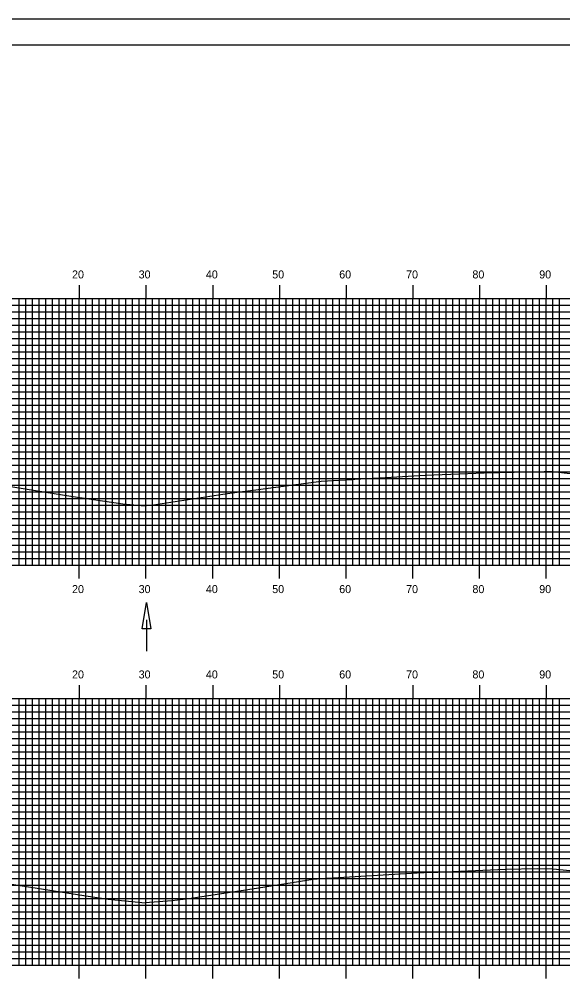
# Model space of a CAD drawing. Extents: x 851926 to 852269, y 366605 to 366825.
# Drawn here: x 852103 to 852184.5, y 366680.6 to 366824.9 of the extents above; entities that cross this region are included whole.
import ezdxf

# ---------------------------------------------------------------- set-up
doc = ezdxf.new("R2010")
doc.units = 0
for name, color, linetype in [('BORDER', 7, 'Continuous'), ('D_Drainage_Ditch_Line', 7, 'Continuous'), ('H_V ANNOTATION', 7, 'Continuous'), ('M_Roadway_Centerline', 7, 'Continuous'), ('MAJOR', 7, 'Continuous'), ('MINOR', 7, 'Continuous'), ('PLOT BOUNDARY', 7, 'Continuous'), ('S_Roadway_Centerline', 7, 'Continuous')]:
    doc.layers.add(name, color=color, linetype=linetype)

msp = doc.modelspace()

# ---------------------------------------------------------------- linework, layer by layer
at = {"layer": 'BORDER'}
msp.add_lwpolyline([(851942.36, 366611.06), (852262.36, 366611.06), (852262.36, 366821.06), (851942.36, 366821.06)], close=True, dxfattribs=at)
at = {"layer": 'D_Drainage_Ditch_Line'}
msp.add_line((852122.03, 366734.83), (852122.03, 366730.13), dxfattribs=at)
msp.add_lwpolyline([(852122.68, 366733.52), (852121.37, 366733.52), (852122.03, 366737.45)], close=True, dxfattribs=at)
at = {"layer": 'MAJOR'}
for p, q in [((852111.96, 366785.06), (852111.96, 366783.06)), ((852121.96, 366785.06), (852121.96, 366783.06)), ((852131.96, 366785.06), (852131.96, 366783.06)), ((852141.96, 366785.06), (852141.96, 366783.06)), ((852151.96, 366785.06), (852151.96, 366783.06)), ((852161.96, 366785.06), (852161.96, 366783.06)), ((852171.96, 366785.06), (852171.96, 366783.06)), ((852181.96, 366785.06), (852181.96, 366783.06)), ((851951.96, 366783.06), (852231.96, 366783.06)), ((851951.96, 366783.06), (852231.96, 366783.06)), ((852111.96, 366743.06), (852111.96, 366783.06)), ((852121.96, 366743.06), (852121.96, 366783.06)), ((852131.96, 366743.06), (852131.96, 366783.06)), ((852141.96, 366743.06), (852141.96, 366783.06)), ((852151.96, 366743.06), (852151.96, 366783.06)), ((852161.96, 366743.06), (852161.96, 366783.06)), ((852171.96, 366743.06), (852171.96, 366783.06)), ((852181.96, 366743.06), (852181.96, 366783.06)), ((851951.96, 366778.06), (852231.96, 366778.06)), ((851951.96, 366773.06), (852231.96, 366773.06)), ((851951.96, 366768.06), (852231.96, 366768.06)), ((851951.96, 366763.06), (852231.96, 366763.06)), ((851951.96, 366758.06), (852231.96, 366758.06)), ((851951.96, 366753.06), (852231.96, 366753.06)), ((851951.96, 366748.06), (852231.96, 366748.06)), ((851951.96, 366743.06), (852231.96, 366743.06)), ((851951.96, 366743.06), (852231.96, 366743.06)), ((852111.96, 366741.05), (852111.96, 366743.06)), ((852121.96, 366741.05), (852121.96, 366743.06)), ((852131.96, 366741.05), (852131.96, 366743.06)), ((852141.96, 366741.05), (852141.96, 366743.06)), ((852151.96, 366741.05), (852151.96, 366743.06)), ((852161.96, 366741.05), (852161.96, 366743.06)), ((852171.96, 366741.05), (852171.96, 366743.06)), ((852181.96, 366741.05), (852181.96, 366743.06)), ((852111.96, 366725.06), (852111.96, 366723.06)), ((852121.96, 366725.06), (852121.96, 366723.06)), ((852131.96, 366725.06), (852131.96, 366723.06)), ((852141.96, 366725.06), (852141.96, 366723.06)), ((852151.96, 366725.06), (852151.96, 366723.06)), ((852161.96, 366725.06), (852161.96, 366723.06)), ((852171.96, 366725.06), (852171.96, 366723.06)), ((852181.96, 366725.06), (852181.96, 366723.06)), ((851951.96, 366723.06), (852231.96, 366723.06)), ((851951.96, 366723.06), (852231.96, 366723.06)), ((852111.96, 366683.06), (852111.96, 366723.06)), ((852121.96, 366683.06), (852121.96, 366723.06)), ((852131.96, 366683.06), (852131.96, 366723.06)), ((852141.96, 366683.06), (852141.96, 366723.06)), ((852151.96, 366683.06), (852151.96, 366723.06)), ((852161.96, 366683.06), (852161.96, 366723.06)), ((852171.96, 366683.06), (852171.96, 366723.06)), ((852181.96, 366683.06), (852181.96, 366723.06)), ((851951.96, 366718.06), (852231.96, 366718.06)), ((851951.96, 366713.06), (852231.96, 366713.06)), ((851951.96, 366708.06), (852231.96, 366708.06)), ((851951.96, 366703.06), (852231.96, 366703.06)), ((851951.96, 366698.06), (852231.96, 366698.06)), ((851951.96, 366693.06), (852231.96, 366693.06)), ((851951.96, 366688.06), (852231.96, 366688.06)), ((851951.96, 366683.06), (852231.96, 366683.06)), ((851951.96, 366683.06), (852231.96, 366683.06)), ((852111.96, 366681.05), (852111.96, 366683.06)), ((852121.96, 366681.05), (852121.96, 366683.06)), ((852131.96, 366681.05), (852131.96, 366683.06)), ((852141.96, 366681.05), (852141.96, 366683.06)), ((852151.96, 366681.05), (852151.96, 366683.06)), ((852161.96, 366681.05), (852161.96, 366683.06)), ((852171.96, 366681.05), (852171.96, 366683.06)), ((852181.96, 366681.05), (852181.96, 366683.06))]:
    msp.add_line(p, q, dxfattribs=at)
at = {"layer": 'MINOR'}
for p, q in [((852102.96, 366743.06), (852102.96, 366783.06)), ((852103.96, 366743.06), (852103.96, 366783.06)), ((852104.96, 366743.06), (852104.96, 366783.06)), ((852105.96, 366743.06), (852105.96, 366783.06)), ((852106.96, 366743.06), (852106.96, 366783.06)), ((852107.96, 366743.06), (852107.96, 366783.06)), ((852108.96, 366743.06), (852108.96, 366783.06)), ((852109.96, 366743.06), (852109.96, 366783.06)), ((852110.96, 366743.06), (852110.96, 366783.06)), ((852112.96, 366743.06), (852112.96, 366783.06)), ((852113.96, 366743.06), (852113.96, 366783.06)), ((852114.96, 366743.06), (852114.96, 366783.06)), ((852115.96, 366743.06), (852115.96, 366783.06)), ((852116.96, 366743.06), (852116.96, 366783.06)), ((852117.96, 366743.06), (852117.96, 366783.06)), ((852118.96, 366743.06), (852118.96, 366783.06)), ((852119.96, 366743.06), (852119.96, 366783.06)), ((852120.96, 366743.06), (852120.96, 366783.06)), ((852122.96, 366743.06), (852122.96, 366783.06)), ((852123.96, 366743.06), (852123.96, 366783.06)), ((852124.96, 366743.06), (852124.96, 366783.06)), ((852125.96, 366743.06), (852125.96, 366783.06)), ((852126.96, 366743.06), (852126.96, 366783.06)), ((852127.96, 366743.06), (852127.96, 366783.06)), ((852128.96, 366743.06), (852128.96, 366783.06)), ((852129.96, 366743.06), (852129.96, 366783.06)), ((852130.96, 366743.06), (852130.96, 366783.06)), ((852132.96, 366743.06), (852132.96, 366783.06)), ((852133.96, 366743.06), (852133.96, 366783.06)), ((852134.96, 366743.06), (852134.96, 366783.06)), ((852135.96, 366743.06), (852135.96, 366783.06)), ((852136.96, 366743.06), (852136.96, 366783.06)), ((852137.96, 366743.06), (852137.96, 366783.06)), ((852138.96, 366743.06), (852138.96, 366783.06)), ((852139.96, 366743.06), (852139.96, 366783.06)), ((852140.96, 366743.06), (852140.96, 366783.06)), ((852142.96, 366743.06), (852142.96, 366783.06)), ((852143.96, 366743.06), (852143.96, 366783.06)), ((852144.96, 366743.06), (852144.96, 366783.06)), ((852145.96, 366743.06), (852145.96, 366783.06)), ((852146.96, 366743.06), (852146.96, 366783.06)), ((852147.96, 366743.06), (852147.96, 366783.06)), ((852148.96, 366743.06), (852148.96, 366783.06)), ((852149.96, 366743.06), (852149.96, 366783.06)), ((852150.96, 366743.06), (852150.96, 366783.06)), ((852152.96, 366743.06), (852152.96, 366783.06)), ((852153.96, 366743.06), (852153.96, 366783.06)), ((852154.96, 366743.06), (852154.96, 366783.06)), ((852155.96, 366743.06), (852155.96, 366783.06)), ((852156.96, 366743.06), (852156.96, 366783.06)), ((852157.96, 366743.06), (852157.96, 366783.06)), ((852158.96, 366743.06), (852158.96, 366783.06)), ((852159.96, 366743.06), (852159.96, 366783.06)), ((852160.96, 366743.06), (852160.96, 366783.06)), ((852162.96, 366743.06), (852162.96, 366783.06)), ((852163.96, 366743.06), (852163.96, 366783.06)), ((852164.96, 366743.06), (852164.96, 366783.06)), ((852165.96, 366743.06), (852165.96, 366783.06)), ((852166.96, 366743.06), (852166.96, 366783.06)), ((852167.96, 366743.06), (852167.96, 366783.06)), ((852168.96, 366743.06), (852168.96, 366783.06)), ((852169.96, 366743.06), (852169.96, 366783.06)), ((852170.96, 366743.06), (852170.96, 366783.06)), ((852172.96, 366743.06), (852172.96, 366783.06)), ((852173.96, 366743.06), (852173.96, 366783.06)), ((852174.96, 366743.06), (852174.96, 366783.06)), ((852175.96, 366743.06), (852175.96, 366783.06)), ((852176.96, 366743.06), (852176.96, 366783.06)), ((852177.96, 366743.06), (852177.96, 366783.06)), ((852178.96, 366743.06), (852178.96, 366783.06)), ((852179.96, 366743.06), (852179.96, 366783.06)), ((852180.96, 366743.06), (852180.96, 366783.06)), ((852182.96, 366743.06), (852182.96, 366783.06)), ((852183.96, 366743.06), (852183.96, 366783.06)), ((851951.96, 366782.06), (852231.96, 366782.06)), ((851951.96, 366781.06), (852231.96, 366781.06)), ((851951.96, 366780.06), (852231.96, 366780.06)), ((851951.96, 366779.06), (852231.96, 366779.06)), ((851951.96, 366777.06), (852231.96, 366777.06)), ((851951.96, 366776.06), (852231.96, 366776.06)), ((851951.96, 366775.06), (852231.96, 366775.06)), ((851951.96, 366774.06), (852231.96, 366774.06)), ((851951.96, 366772.06), (852231.96, 366772.06)), ((851951.96, 366771.06), (852231.96, 366771.06)), ((851951.96, 366770.06), (852231.96, 366770.06)), ((851951.96, 366769.06), (852231.96, 366769.06)), ((851951.96, 366767.06), (852231.96, 366767.06)), ((851951.96, 366766.06), (852231.96, 366766.06)), ((851951.96, 366765.06), (852231.96, 366765.06)), ((851951.96, 366764.06), (852231.96, 366764.06)), ((851951.96, 366762.06), (852231.96, 366762.06)), ((851951.96, 366761.06), (852231.96, 366761.06)), ((851951.96, 366760.06), (852231.96, 366760.06)), ((851951.96, 366759.06), (852231.96, 366759.06)), ((851951.96, 366757.06), (852231.96, 366757.06)), ((851951.96, 366756.06), (852231.96, 366756.06)), ((851951.96, 366755.06), (852231.96, 366755.06)), ((851951.96, 366754.06), (852231.96, 366754.06)), ((851951.96, 366752.06), (852231.96, 366752.06)), ((851951.96, 366751.06), (852231.96, 366751.06)), ((851951.96, 366750.06), (852231.96, 366750.06)), ((851951.96, 366749.06), (852231.96, 366749.06)), ((851951.96, 366747.06), (852231.96, 366747.06)), ((851951.96, 366746.06), (852231.96, 366746.06)), ((851951.96, 366745.06), (852231.96, 366745.06)), ((851951.96, 366744.06), (852231.96, 366744.06)), ((851951.96, 366722.06), (852231.96, 366722.06)), ((852102.96, 366683.06), (852102.96, 366723.06)), ((852103.96, 366683.06), (852103.96, 366723.06)), ((852104.96, 366683.06), (852104.96, 366723.06)), ((852105.96, 366683.06), (852105.96, 366723.06)), ((852106.96, 366683.06), (852106.96, 366723.06)), ((852107.96, 366683.06), (852107.96, 366723.06)), ((852108.96, 366683.06), (852108.96, 366723.06)), ((852109.96, 366683.06), (852109.96, 366723.06)), ((852110.96, 366683.06), (852110.96, 366723.06)), ((852112.96, 366683.06), (852112.96, 366723.06)), ((852113.96, 366683.06), (852113.96, 366723.06)), ((852114.96, 366683.06), (852114.96, 366723.06)), ((852115.96, 366683.06), (852115.96, 366723.06)), ((852116.96, 366683.06), (852116.96, 366723.06)), ((852117.96, 366683.06), (852117.96, 366723.06)), ((852118.96, 366683.06), (852118.96, 366723.06)), ((852119.96, 366683.06), (852119.96, 366723.06)), ((852120.96, 366683.06), (852120.96, 366723.06)), ((852122.96, 366683.06), (852122.96, 366723.06)), ((852123.96, 366683.06), (852123.96, 366723.06)), ((852124.96, 366683.06), (852124.96, 366723.06)), ((852125.96, 366683.06), (852125.96, 366723.06)), ((852126.96, 366683.06), (852126.96, 366723.06)), ((852127.96, 366683.06), (852127.96, 366723.06)), ((852128.96, 366683.06), (852128.96, 366723.06)), ((852129.96, 366683.06), (852129.96, 366723.06)), ((852130.96, 366683.06), (852130.96, 366723.06)), ((852132.96, 366683.06), (852132.96, 366723.06)), ((852133.96, 366683.06), (852133.96, 366723.06)), ((852134.96, 366683.06), (852134.96, 366723.06)), ((852135.96, 366683.06), (852135.96, 366723.06)), ((852136.96, 366683.06), (852136.96, 366723.06)), ((852137.96, 366683.06), (852137.96, 366723.06)), ((852138.96, 366683.06), (852138.96, 366723.06)), ((852139.96, 366683.06), (852139.96, 366723.06)), ((852140.96, 366683.06), (852140.96, 366723.06)), ((852142.96, 366683.06), (852142.96, 366723.06)), ((852143.96, 366683.06), (852143.96, 366723.06)), ((852144.96, 366683.06), (852144.96, 366723.06)), ((852145.96, 366683.06), (852145.96, 366723.06)), ((852146.96, 366683.06), (852146.96, 366723.06)), ((852147.96, 366683.06), (852147.96, 366723.06)), ((852148.96, 366683.06), (852148.96, 366723.06)), ((852149.96, 366683.06), (852149.96, 366723.06)), ((852150.96, 366683.06), (852150.96, 366723.06)), ((852152.96, 366683.06), (852152.96, 366723.06)), ((852153.96, 366683.06), (852153.96, 366723.06)), ((852154.96, 366683.06), (852154.96, 366723.06)), ((852155.96, 366683.06), (852155.96, 366723.06)), ((852156.96, 366683.06), (852156.96, 366723.06)), ((852157.96, 366683.06), (852157.96, 366723.06)), ((852158.96, 366683.06), (852158.96, 366723.06)), ((852159.96, 366683.06), (852159.96, 366723.06)), ((852160.96, 366683.06), (852160.96, 366723.06)), ((852162.96, 366683.06), (852162.96, 366723.06)), ((852163.96, 366683.06), (852163.96, 366723.06)), ((852164.96, 366683.06), (852164.96, 366723.06)), ((852165.96, 366683.06), (852165.96, 366723.06)), ((852166.96, 366683.06), (852166.96, 366723.06)), ((852167.96, 366683.06), (852167.96, 366723.06)), ((852168.96, 366683.06), (852168.96, 366723.06)), ((852169.96, 366683.06), (852169.96, 366723.06)), ((852170.96, 366683.06), (852170.96, 366723.06)), ((852172.96, 366683.06), (852172.96, 366723.06)), ((852173.96, 366683.06), (852173.96, 366723.06)), ((852174.96, 366683.06), (852174.96, 366723.06)), ((852175.96, 366683.06), (852175.96, 366723.06)), ((852176.96, 366683.06), (852176.96, 366723.06)), ((852177.96, 366683.06), (852177.96, 366723.06)), ((852178.96, 366683.06), (852178.96, 366723.06)), ((852179.96, 366683.06), (852179.96, 366723.06)), ((852180.96, 366683.06), (852180.96, 366723.06)), ((852182.96, 366683.06), (852182.96, 366723.06)), ((852183.96, 366683.06), (852183.96, 366723.06)), ((851951.96, 366721.06), (852231.96, 366721.06)), ((851951.96, 366720.06), (852231.96, 366720.06)), ((851951.96, 366719.06), (852231.96, 366719.06)), ((851951.96, 366717.06), (852231.96, 366717.06)), ((851951.96, 366716.06), (852231.96, 366716.06)), ((851951.96, 366715.06), (852231.96, 366715.06)), ((851951.96, 366714.06), (852231.96, 366714.06)), ((851951.96, 366712.06), (852231.96, 366712.06)), ((851951.96, 366711.06), (852231.96, 366711.06)), ((851951.96, 366710.06), (852231.96, 366710.06)), ((851951.96, 366709.06), (852231.96, 366709.06)), ((851951.96, 366707.06), (852231.96, 366707.06)), ((851951.96, 366706.06), (852231.96, 366706.06)), ((851951.96, 366705.06), (852231.96, 366705.06)), ((851951.96, 366704.06), (852231.96, 366704.06)), ((851951.96, 366702.06), (852231.96, 366702.06)), ((851951.96, 366701.06), (852231.96, 366701.06)), ((851951.96, 366700.06), (852231.96, 366700.06)), ((851951.96, 366699.06), (852231.96, 366699.06)), ((851951.96, 366697.06), (852231.96, 366697.06)), ((851951.96, 366696.06), (852231.96, 366696.06)), ((851951.96, 366695.06), (852231.96, 366695.06)), ((851951.96, 366694.06), (852231.96, 366694.06)), ((851951.96, 366692.06), (852231.96, 366692.06)), ((851951.96, 366691.06), (852231.96, 366691.06)), ((851951.96, 366690.06), (852231.96, 366690.06)), ((851951.96, 366689.06), (852231.96, 366689.06)), ((851951.96, 366687.06), (852231.96, 366687.06)), ((851951.96, 366686.06), (852231.96, 366686.06)), ((851951.96, 366685.06), (852231.96, 366685.06)), ((851951.96, 366684.06), (852231.96, 366684.06))]:
    msp.add_line(p, q, dxfattribs=at)
at = {"layer": 'PLOT BOUNDARY'}
msp.add_lwpolyline([(851926.18, 366604.94), (852266.18, 366604.94), (852266.18, 366824.94), (851926.18, 366824.94)], close=True, dxfattribs=at)
at = {"layer": 'S_Roadway_Centerline'}
for points in [[(852099.72, 366755.15), (852110.7, 366753.41), (852118.5, 366752.25), (852121.24, 366752), (852122.02, 366751.99), (852123.08, 366752.08), (852133.47, 366753.68), (852135.62, 366754.02), (852138.01, 366754.32), (852148.21, 366755.66), (852152.88, 366755.91), (852153.28, 366755.93), (852158.75, 366756.23), (852163.85, 366756.54), (852170.23, 366756.82), (852172.69, 366756.92), (852181.7, 366757.11), (852182.95, 366757.11), (852189.15, 366756.39)], [(852101.48, 366695.23), (852103.08, 366695.02), (852112.64, 366693.51), (852116.29, 366692.93), (852121.82, 366692.41), (852121.86, 366692.46), (852125.86, 366692.76), (852128.36, 366693.07), (852137.89, 366694.49), (852147.02, 366695.94), (852148.24, 366696.07), (852163.48, 366696.96), (852163.66, 366696.97), (852163.76, 366696.98), (852163.87, 366696.98), (852165.73, 366697), (852175.86, 366697.45), (852180.62, 366697.55), (852183.01, 366697.51), (852186.05, 366697.2)]]:
    msp.add_lwpolyline(points, dxfattribs=at)

# ---------------------------------------------------------------- texts
at = {"layer": 'H_V ANNOTATION'}
for s, p in [('20', (852110.87, 366786.06)), ('30', (852120.86, 366786.06)), ('40', (852130.94, 366786.06)), ('50', (852140.89, 366786.06)), ('60', (852150.94, 366786.06)), ('70', (852160.97, 366786.06)), ('80', (852170.92, 366786.06)), ('90', (852180.94, 366786.06)), ('20', (852110.87, 366738.86)), ('30', (852120.86, 366738.86)), ('40', (852130.94, 366738.86)), ('50', (852140.89, 366738.86)), ('60', (852150.94, 366738.86)), ('70', (852160.97, 366738.86)), ('80', (852170.92, 366738.86)), ('90', (852180.94, 366738.86)), ('20', (852110.87, 366726.06)), ('30', (852120.86, 366726.06)), ('40', (852130.94, 366726.06)), ('50', (852140.89, 366726.06)), ('60', (852150.94, 366726.06)), ('70', (852160.97, 366726.06)), ('80', (852170.92, 366726.06)), ('90', (852180.94, 366726.06))]:
    msp.add_text(s, height=1.2, dxfattribs=at).set_placement(p)
at = {"layer": 'M_Roadway_Centerline'}
for s, p in [('C', (852163.85, 366756.54)), ('L', (852163.85, 366756.54)), ('C', (852163.76, 366696.98)), ('L', (852163.76, 366696.97))]:
    msp.add_text(s, height=0.0146, dxfattribs=at).set_placement(p)

doc.saveas('drawing.dxf')
